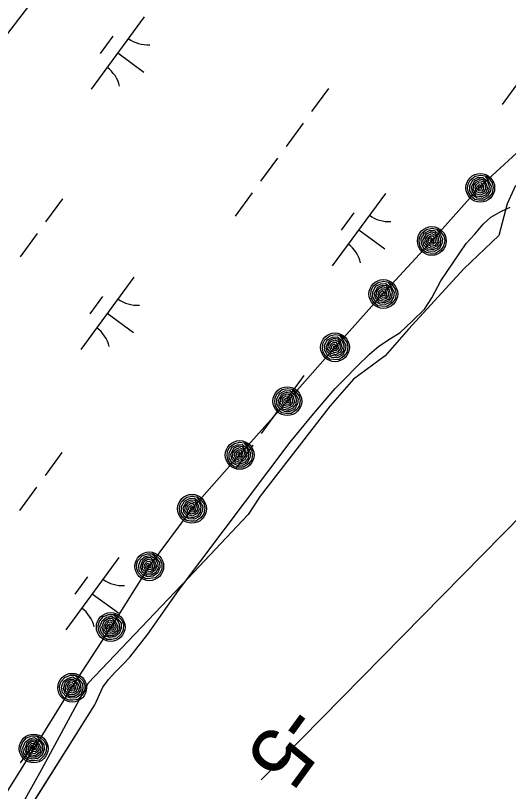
# Model space of a CAD drawing. Extents: x 3905714 to 3926767, y 183354 to 205755.
# Drawn here: x 3911955.9 to 3912230.3, y 187949.4 to 188380.9 of the extents above; entities that cross this region are included whole.
import ezdxf

# ---------------------------------------------------------------- set-up
doc = ezdxf.new("R2010")
doc.units = 0
for name, color, linetype in [('V-RIVR-EDGE', 7, 'Continuous'), ('V-RIVR-RANG', 7, 'Continuous'), ('V-RRAP-FSHR', 7, 'Continuous'), ('V-TOPO-MINR', 7, 'Continuous'), ('V-TOPO-SHOR', 7, 'Continuous'), ('V-UTIL-LINE', 7, 'Continuous'), ('V-WETL-SWMP', 7, 'Continuous')]:
    doc.layers.add(name, color=color, linetype=linetype)

msp = doc.modelspace()

# ---------------------------------------------------------------- linework, layer by layer
at = {"layer": 'V-RIVR-EDGE'}
msp.add_lwpolyline([(3912234.16, 188286.45), (3912229.51, 188276.23), (3912224.87, 188258.58), (3912205.35, 188239.99), (3912174.69, 188206.54), (3912161.68, 188191.67), (3912144.03, 188178.66), (3912131.02, 188163.8), (3912091.99, 188113.62), (3912085.49, 188103.4), (3912052.03, 188068.09), (3911996.28, 188009.55), (3911970.26, 187961.23), (3911928.45, 187886.89), (3911896.86, 187820.92), (3911865.16, 187767.87)], dxfattribs=at)
at = {"layer": 'V-RRAP-FSHR'}
for points in [[(3912243.67, 188312.51), (3912214.58, 188285.92), (3912187.6, 188255.56), (3912160.61, 188226.38), (3912133.74, 188196.41), (3912107.2, 188166.48), (3912080.67, 188136.55), (3912054.13, 188106.62), (3912030.37, 188074.6), (3912008.92, 188040.84), (3911987.47, 188007.77), (3911966.17, 187973.31), (3911944.75, 187939.44), (3911923.63, 187905.47), (3911902.52, 187871.49), (3911881.6, 187837.4), (3911862.53, 187802.25)], [(3912217.66, 188291.74), (3912219.27, 188290.42), (3912221.25, 188287.82), (3912221.8, 188285.3), (3912221.11, 188282.16), (3912219.41, 188279.99), (3912216.63, 188278.17), (3912213.73, 188278.29), (3912211.48, 188278.6), (3912209.28, 188280.41), (3912207.96, 188282.56), (3912207.55, 188284.88), (3912207.78, 188287.09), (3912208.96, 188289.42), (3912211.72, 188291.53), (3912214.84, 188292.17), (3912217.2, 188291.72), (3912219.18, 188288.8), (3912220.6, 188286.2), (3912220.25, 188283.43), (3912218.61, 188280.64), (3912215.84, 188279.25), (3912212.83, 188279.43), (3912210.39, 188280.79), (3912208.8, 188283.43), (3912208.75, 188286.41), (3912210.48, 188289.39), (3912213.25, 188290.81), (3912216.04, 188290.92), (3912218.58, 188288.71), (3912219.49, 188286.1), (3912219.2, 188283.27), (3912217.54, 188281.07), (3912215.08, 188280.11), (3912212.34, 188280.5), (3912210.21, 188282.81), (3912209.67, 188285.6), (3912211.55, 188289), (3912214.17, 188290.09), (3912216.05, 188289.76), (3912217.92, 188287.34), (3912218.56, 188284.53), (3912217.5, 188282.33), (3912214.79, 188280.96), (3912212.52, 188281.65), (3912210.63, 188284.09), (3912211.02, 188286.47), (3912212.55, 188288.36), (3912214.54, 188289.2), (3912216.42, 188288.35), (3912217.21, 188286.52), (3912217.5, 188284.23), (3912216.18, 188282.62), (3912214.3, 188282.08), (3912212.35, 188283.07), (3912211.69, 188284.86), (3912212.11, 188286.58), (3912213.83, 188287.98), (3912215.16, 188287.92), (3912216.23, 188286.23), (3912216.38, 188284.31), (3912215.43, 188283.23), (3912213.87, 188283.35), (3912212.55, 188284.67), (3912213, 188286.25), (3912214.12, 188286.96), (3912215.41, 188285.94), (3912215.34, 188284.3), (3912214.17, 188284.23), (3912213.68, 188285.26), (3912214.08, 188286.01), (3912214.62, 188285.12)], [(3912190.67, 188262.21), (3912192.29, 188260.9), (3912194.27, 188258.29), (3912194.82, 188255.77), (3912194.13, 188252.63), (3912192.42, 188250.46), (3912189.65, 188248.64), (3912186.74, 188248.76), (3912184.49, 188249.07), (3912182.3, 188250.88), (3912180.98, 188253.04), (3912180.57, 188255.36), (3912180.8, 188257.56), (3912181.98, 188259.89), (3912184.74, 188262.01), (3912187.86, 188262.64), (3912190.22, 188262.19), (3912192.19, 188259.28), (3912193.62, 188256.67), (3912193.26, 188253.9), (3912191.63, 188251.11), (3912188.85, 188249.72), (3912185.84, 188249.9), (3912183.4, 188251.26), (3912181.81, 188253.9), (3912181.76, 188256.88), (3912183.49, 188259.86), (3912186.26, 188261.29), (3912189.05, 188261.39), (3912191.6, 188259.19), (3912192.5, 188256.58), (3912192.21, 188253.75), (3912190.55, 188251.54), (3912188.09, 188250.58), (3912185.36, 188250.98), (3912183.23, 188253.28), (3912182.69, 188256.07), (3912184.56, 188259.47), (3912187.19, 188260.56), (3912189.06, 188260.23), (3912190.93, 188257.81), (3912191.58, 188255), (3912190.52, 188252.8), (3912187.8, 188251.44), (3912185.54, 188252.12), (3912183.65, 188254.56), (3912184.04, 188256.94), (3912185.57, 188258.83), (3912187.56, 188259.67), (3912189.44, 188258.82), (3912190.23, 188256.99), (3912190.52, 188254.71), (3912189.2, 188253.09), (3912187.32, 188252.55), (3912185.37, 188253.54), (3912184.71, 188255.34), (3912185.13, 188257.05), (3912186.85, 188258.46), (3912188.17, 188258.39), (3912189.25, 188256.7), (3912189.39, 188254.78), (3912188.45, 188253.7), (3912186.89, 188253.82), (3912185.57, 188255.15), (3912186.01, 188256.72), (3912187.14, 188257.43), (3912188.43, 188256.42), (3912188.36, 188254.77), (3912187.18, 188254.7), (3912186.7, 188255.74), (3912187.1, 188256.48), (3912187.64, 188255.59)], [(3912163.69, 188232.68), (3912165.3, 188231.37), (3912167.28, 188228.77), (3912167.83, 188226.24), (3912167.14, 188223.11), (3912165.44, 188220.94), (3912162.66, 188219.11), (3912159.76, 188219.23), (3912157.51, 188219.55), (3912155.31, 188221.35), (3912154, 188223.51), (3912153.58, 188225.83), (3912153.81, 188228.04), (3912154.99, 188230.37), (3912157.76, 188232.48), (3912160.88, 188233.12), (3912163.23, 188232.66), (3912165.21, 188229.75), (3912166.63, 188227.14), (3912166.28, 188224.37), (3912164.65, 188221.58), (3912161.87, 188220.2), (3912158.86, 188220.37), (3912156.42, 188221.73), (3912154.83, 188224.37), (3912154.78, 188227.35), (3912156.51, 188230.33), (3912159.28, 188231.76), (3912162.07, 188231.86), (3912164.61, 188229.66), (3912165.52, 188227.05), (3912165.23, 188224.22), (3912163.57, 188222.01), (3912161.11, 188221.05), (3912158.38, 188221.45), (3912156.24, 188223.75), (3912155.7, 188226.55), (3912157.58, 188229.94), (3912160.2, 188231.04), (3912162.08, 188230.71), (3912163.95, 188228.28), (3912164.59, 188225.48), (3912163.53, 188223.27), (3912160.82, 188221.91), (3912158.55, 188222.6), (3912156.66, 188225.04), (3912157.05, 188227.41), (3912158.58, 188229.31), (3912160.57, 188230.14), (3912162.46, 188229.29), (3912163.24, 188227.46), (3912163.53, 188225.18), (3912162.22, 188223.57), (3912160.33, 188223.03), (3912158.39, 188224.02), (3912157.72, 188225.81), (3912158.14, 188227.53), (3912159.86, 188228.93), (3912161.19, 188228.86), (3912162.26, 188227.17), (3912162.41, 188225.25), (3912161.46, 188224.18), (3912159.91, 188224.29), (3912158.58, 188225.62), (3912159.03, 188227.19), (3912160.16, 188227.91), (3912161.45, 188226.89), (3912161.37, 188225.25), (3912160.2, 188225.18), (3912159.71, 188226.21), (3912160.12, 188226.95), (3912160.65, 188226.07)], [(3912136.71, 188203.1), (3912138.35, 188201.81), (3912140.37, 188199.24), (3912140.95, 188196.73), (3912140.31, 188193.58), (3912138.64, 188191.39), (3912135.89, 188189.52), (3912132.99, 188189.59), (3912130.73, 188189.87), (3912128.51, 188191.65), (3912127.16, 188193.78), (3912126.71, 188196.1), (3912126.91, 188198.31), (3912128.05, 188200.65), (3912130.78, 188202.81), (3912133.89, 188203.49), (3912136.26, 188203.08), (3912138.28, 188200.19), (3912139.74, 188197.61), (3912139.43, 188194.83), (3912137.84, 188192.02), (3912135.08, 188190.59), (3912132.07, 188190.72), (3912129.61, 188192.04), (3912127.98, 188194.66), (3912127.88, 188197.64), (3912129.57, 188200.64), (3912132.32, 188202.11), (3912135.11, 188202.26), (3912137.68, 188200.09), (3912138.63, 188197.5), (3912138.38, 188194.66), (3912136.75, 188192.43), (3912134.31, 188191.43), (3912131.57, 188191.79), (3912129.4, 188194.06), (3912128.82, 188196.85), (3912130.65, 188200.27), (3912133.25, 188201.4), (3912135.14, 188201.1), (3912137.04, 188198.71), (3912137.73, 188195.91), (3912136.7, 188193.69), (3912134.01, 188192.29), (3912131.73, 188192.94), (3912129.8, 188195.35), (3912130.16, 188197.73), (3912131.66, 188199.65), (3912133.64, 188200.51), (3912135.53, 188199.7), (3912136.35, 188197.88), (3912136.67, 188195.6), (3912135.38, 188193.97), (3912133.5, 188193.4), (3912131.54, 188194.36), (3912130.85, 188196.14), (3912131.25, 188197.86), (3912132.94, 188199.29), (3912134.27, 188199.25), (3912135.37, 188197.57), (3912135.55, 188195.65), (3912134.62, 188194.56), (3912133.06, 188194.65), (3912131.71, 188195.96), (3912132.14, 188197.54), (3912133.25, 188198.27), (3912134.56, 188197.27), (3912134.51, 188195.63), (3912133.33, 188195.54), (3912132.84, 188196.57), (3912133.23, 188197.32), (3912133.78, 188196.44)], [(3912110.18, 188173.17), (3912111.81, 188171.88), (3912113.83, 188169.31), (3912114.42, 188166.8), (3912113.78, 188163.65), (3912112.11, 188161.45), (3912109.36, 188159.59), (3912106.45, 188159.66), (3912104.2, 188159.94), (3912101.98, 188161.72), (3912100.62, 188163.85), (3912100.18, 188166.17), (3912100.37, 188168.38), (3912101.52, 188170.72), (3912104.25, 188172.88), (3912107.36, 188173.56), (3912109.72, 188173.14), (3912111.74, 188170.26), (3912113.2, 188167.68), (3912112.89, 188164.9), (3912111.3, 188162.09), (3912108.55, 188160.66), (3912105.53, 188160.79), (3912103.07, 188162.11), (3912101.44, 188164.73), (3912101.35, 188167.71), (3912103.03, 188170.71), (3912105.78, 188172.18), (3912108.57, 188172.33), (3912111.15, 188170.16), (3912112.09, 188167.57), (3912111.85, 188164.73), (3912110.22, 188162.5), (3912107.77, 188161.5), (3912105.04, 188161.86), (3912102.87, 188164.13), (3912102.29, 188166.92), (3912104.11, 188170.34), (3912106.72, 188171.47), (3912108.6, 188171.17), (3912110.5, 188168.78), (3912111.19, 188165.98), (3912110.16, 188163.76), (3912107.47, 188162.36), (3912105.19, 188163.01), (3912103.27, 188165.42), (3912103.62, 188167.8), (3912105.12, 188169.72), (3912107.1, 188170.58), (3912109, 188169.76), (3912109.81, 188167.95), (3912110.13, 188165.67), (3912108.84, 188164.04), (3912106.97, 188163.47), (3912105, 188164.43), (3912104.32, 188166.21), (3912104.71, 188167.93), (3912106.41, 188169.36), (3912107.74, 188169.32), (3912108.83, 188167.64), (3912109.01, 188165.72), (3912108.08, 188164.63), (3912106.52, 188164.73), (3912105.18, 188166.03), (3912105.6, 188167.61), (3912106.72, 188168.34), (3912108.02, 188167.34), (3912107.98, 188165.7), (3912106.8, 188165.61), (3912106.3, 188166.64), (3912106.69, 188167.39), (3912107.24, 188166.51)], [(3912083.64, 188143.24), (3912085.27, 188141.95), (3912087.29, 188139.38), (3912087.88, 188136.86), (3912087.24, 188133.72), (3912085.57, 188131.52), (3912082.82, 188129.66), (3912079.92, 188129.73), (3912077.66, 188130.01), (3912075.44, 188131.79), (3912074.09, 188133.92), (3912073.64, 188136.24), (3912073.84, 188138.45), (3912074.98, 188140.79), (3912077.71, 188142.95), (3912080.82, 188143.63), (3912083.19, 188143.21), (3912085.21, 188140.33), (3912086.67, 188137.74), (3912086.36, 188134.97), (3912084.77, 188132.16), (3912082.01, 188130.73), (3912079, 188130.86), (3912076.54, 188132.18), (3912074.91, 188134.8), (3912074.81, 188137.78), (3912076.5, 188140.78), (3912079.25, 188142.25), (3912082.04, 188142.4), (3912084.61, 188140.23), (3912085.56, 188137.64), (3912085.31, 188134.8), (3912083.68, 188132.57), (3912081.23, 188131.57), (3912078.5, 188131.93), (3912076.33, 188134.2), (3912075.75, 188136.99), (3912077.58, 188140.41), (3912080.18, 188141.54), (3912082.06, 188141.24), (3912083.97, 188138.85), (3912084.66, 188136.05), (3912083.63, 188133.83), (3912080.94, 188132.43), (3912078.66, 188133.08), (3912076.73, 188135.49), (3912077.08, 188137.87), (3912078.59, 188139.79), (3912080.56, 188140.65), (3912082.46, 188139.83), (3912083.27, 188138.02), (3912083.6, 188135.74), (3912082.31, 188134.11), (3912080.43, 188133.54), (3912078.47, 188134.49), (3912077.78, 188136.28), (3912078.18, 188138), (3912079.87, 188139.43), (3912081.2, 188139.39), (3912082.3, 188137.71), (3912082.47, 188135.79), (3912081.54, 188134.7), (3912079.98, 188134.79), (3912078.64, 188136.1), (3912079.06, 188137.68), (3912080.18, 188138.41), (3912081.48, 188137.41), (3912081.44, 188135.77), (3912080.26, 188135.68), (3912079.77, 188136.71), (3912080.16, 188137.46), (3912080.71, 188136.58)], [(3912057.11, 188113.31), (3912058.74, 188112.02), (3912060.76, 188109.45), (3912061.35, 188106.93), (3912060.71, 188103.79), (3912059.03, 188101.59), (3912056.29, 188099.73), (3912053.38, 188099.8), (3912051.12, 188100.08), (3912048.9, 188101.86), (3912047.55, 188103.99), (3912047.1, 188106.3), (3912047.3, 188108.52), (3912048.45, 188110.86), (3912051.18, 188113.02), (3912054.29, 188113.7), (3912056.65, 188113.28), (3912058.67, 188110.4), (3912060.13, 188107.81), (3912059.82, 188105.04), (3912058.23, 188102.23), (3912055.48, 188100.8), (3912052.46, 188100.93), (3912050, 188102.25), (3912048.37, 188104.87), (3912048.27, 188107.85), (3912049.96, 188110.85), (3912052.71, 188112.32), (3912055.5, 188112.47), (3912058.08, 188110.3), (3912059.02, 188107.71), (3912058.77, 188104.87), (3912057.15, 188102.64), (3912054.7, 188101.64), (3912051.96, 188102), (3912049.79, 188104.27), (3912049.21, 188107.05), (3912051.04, 188110.48), (3912053.64, 188111.61), (3912055.53, 188111.31), (3912057.43, 188108.92), (3912058.12, 188106.12), (3912057.09, 188103.9), (3912054.4, 188102.5), (3912052.12, 188103.15), (3912050.19, 188105.56), (3912050.55, 188107.94), (3912052.05, 188109.86), (3912054.03, 188110.72), (3912055.92, 188109.9), (3912056.74, 188108.09), (3912057.06, 188105.81), (3912055.77, 188104.17), (3912053.9, 188103.61), (3912051.93, 188104.57), (3912051.25, 188106.35), (3912051.64, 188108.07), (3912053.34, 188109.5), (3912054.67, 188109.46), (3912055.76, 188107.78), (3912055.94, 188105.86), (3912055.01, 188104.77), (3912053.45, 188104.86), (3912052.11, 188106.17), (3912052.53, 188107.75), (3912053.65, 188108.48), (3912054.95, 188107.48), (3912054.9, 188105.84), (3912053.73, 188105.75), (3912053.23, 188106.78), (3912053.62, 188107.53), (3912054.17, 188106.65)], [(3912032.24, 188081.68), (3912034.06, 188080.67), (3912036.46, 188078.45), (3912037.44, 188076.06), (3912037.31, 188072.85), (3912036, 188070.42), (3912033.59, 188068.14), (3912030.71, 188067.75), (3912028.44, 188067.67), (3912025.96, 188069.07), (3912024.29, 188070.96), (3912023.48, 188073.18), (3912023.32, 188075.39), (3912024.08, 188077.89), (3912026.43, 188080.45), (3912029.39, 188081.62), (3912031.8, 188081.58), (3912034.25, 188079.05), (3912036.1, 188076.73), (3912036.23, 188073.95), (3912035.11, 188070.92), (3912032.62, 188069.07), (3912029.62, 188068.72), (3912026.98, 188069.63), (3912024.96, 188071.96), (3912024.39, 188074.89), (3912025.58, 188078.12), (3912028.06, 188080.01), (3912030.79, 188080.59), (3912033.68, 188078.86), (3912035.02, 188076.45), (3912035.23, 188073.61), (3912033.98, 188071.15), (3912031.72, 188069.78), (3912028.96, 188069.69), (3912026.46, 188071.59), (3912025.44, 188074.25), (3912026.7, 188077.92), (3912029.09, 188079.45), (3912031, 188079.45), (3912033.26, 188077.39), (3912034.38, 188074.74), (3912033.72, 188072.39), (3912031.29, 188070.57), (3912028.93, 188070.85), (3912026.65, 188072.93), (3912026.62, 188075.34), (3912027.8, 188077.47), (3912029.61, 188078.64), (3912031.61, 188078.13), (3912032.71, 188076.46), (3912033.39, 188074.26), (3912032.37, 188072.45), (3912030.61, 188071.59), (3912028.52, 188072.22), (3912027.56, 188073.88), (3912027.68, 188075.64), (3912029.12, 188077.32), (3912030.44, 188077.49), (3912031.79, 188076.01), (3912032.27, 188074.14), (3912031.53, 188072.92), (3912029.97, 188072.76), (3912028.44, 188073.84), (3912028.6, 188075.46), (3912029.59, 188076.36), (3912031.04, 188075.58), (3912031.25, 188073.96), (3912030.1, 188073.68), (3912029.45, 188074.61), (3912029.72, 188075.42), (3912030.4, 188074.64)], [(3912010.79, 188047.92), (3912012.61, 188046.9), (3912015.01, 188044.68), (3912015.99, 188042.3), (3912015.86, 188039.08), (3912014.56, 188036.65), (3912012.14, 188034.38), (3912009.26, 188033.99), (3912006.99, 188033.91), (3912004.51, 188035.3), (3912002.84, 188037.2), (3912002.03, 188039.41), (3912001.87, 188041.63), (3912002.63, 188044.13), (3912004.98, 188046.69), (3912007.95, 188047.86), (3912010.35, 188047.82), (3912012.8, 188045.29), (3912014.65, 188042.97), (3912014.79, 188040.18), (3912013.66, 188037.15), (3912011.17, 188035.3), (3912008.17, 188034.96), (3912005.53, 188035.87), (3912003.51, 188038.2), (3912002.94, 188041.12), (3912004.13, 188044.35), (3912006.61, 188046.24), (3912009.34, 188046.83), (3912012.23, 188045.1), (3912013.57, 188042.69), (3912013.78, 188039.85), (3912012.53, 188037.39), (3912010.27, 188036.02), (3912007.51, 188035.93), (3912005.01, 188037.83), (3912003.99, 188040.49), (3912005.25, 188044.16), (3912007.64, 188045.69), (3912009.55, 188045.69), (3912011.81, 188043.63), (3912012.93, 188040.98), (3912012.27, 188038.62), (3912009.84, 188036.81), (3912007.48, 188037.09), (3912005.2, 188039.17), (3912005.17, 188041.58), (3912006.35, 188043.71), (3912008.17, 188044.87), (3912010.16, 188044.36), (3912011.26, 188042.7), (3912011.94, 188040.5), (3912010.92, 188038.68), (3912009.16, 188037.83), (3912007.07, 188038.46), (3912006.11, 188040.11), (3912006.23, 188041.88), (3912007.67, 188043.56), (3912008.99, 188043.72), (3912010.34, 188042.24), (3912010.82, 188040.38), (3912010.08, 188039.15), (3912008.52, 188039), (3912006.99, 188040.08), (3912007.16, 188041.7), (3912008.14, 188042.6), (3912009.59, 188041.82), (3912009.8, 188040.19), (3912008.66, 188039.92), (3912008, 188040.85), (3912008.27, 188041.65), (3912008.95, 188040.87)], [(3911989.34, 188014.15), (3911991.16, 188013.14), (3911993.56, 188010.92), (3911994.54, 188008.53), (3911994.41, 188005.32), (3911993.11, 188002.89), (3911990.69, 188000.61), (3911987.81, 188000.23), (3911985.54, 188000.14), (3911983.06, 188001.54), (3911981.39, 188003.44), (3911980.58, 188005.65), (3911980.42, 188007.86), (3911981.18, 188010.36), (3911983.53, 188012.92), (3911986.5, 188014.09), (3911988.9, 188014.06), (3911991.35, 188011.53), (3911993.2, 188009.21), (3911993.34, 188006.42), (3911992.21, 188003.39), (3911989.72, 188001.54), (3911986.72, 188001.19), (3911984.08, 188002.11), (3911982.06, 188004.43), (3911981.49, 188007.36), (3911982.68, 188010.59), (3911985.16, 188012.48), (3911987.89, 188013.07), (3911990.78, 188011.34), (3911992.12, 188008.93), (3911992.33, 188006.09), (3911991.08, 188003.63), (3911988.82, 188002.25), (3911986.06, 188002.17), (3911983.56, 188004.07), (3911982.54, 188006.73), (3911983.8, 188010.4), (3911986.19, 188011.93), (3911988.1, 188011.93), (3911990.36, 188009.87), (3911991.48, 188007.21), (3911990.82, 188004.86), (3911988.39, 188003.05), (3911986.04, 188003.33), (3911983.75, 188005.4), (3911983.72, 188007.81), (3911984.9, 188009.94), (3911986.71, 188011.11), (3911988.71, 188010.6), (3911989.81, 188008.94), (3911990.49, 188006.74), (3911989.47, 188004.92), (3911987.71, 188004.06), (3911985.62, 188004.7), (3911984.66, 188006.35), (3911984.78, 188008.11), (3911986.23, 188009.79), (3911987.54, 188009.96), (3911988.89, 188008.48), (3911989.37, 188006.62), (3911988.63, 188005.39), (3911987.07, 188005.23), (3911985.54, 188006.31), (3911985.71, 188007.94), (3911986.69, 188008.84), (3911988.14, 188008.06), (3911988.35, 188006.43), (3911987.21, 188006.15), (3911986.55, 188007.09), (3911986.82, 188007.89), (3911987.5, 188007.11)], [(3911967.89, 187980.39), (3911969.71, 187979.38), (3911972.11, 187977.16), (3911973.09, 187974.77), (3911972.96, 187971.56), (3911971.66, 187969.13), (3911969.24, 187966.85), (3911966.36, 187966.46), (3911964.09, 187966.38), (3911961.61, 187967.78), (3911959.94, 187969.67), (3911959.13, 187971.89), (3911958.97, 187974.1), (3911959.73, 187976.6), (3911962.08, 187979.16), (3911965.05, 187980.33), (3911967.45, 187980.29), (3911969.9, 187977.77), (3911971.75, 187975.45), (3911971.89, 187972.66), (3911970.76, 187969.63), (3911968.27, 187967.78), (3911965.27, 187967.43), (3911962.63, 187968.35), (3911960.61, 187970.67), (3911960.04, 187973.6), (3911961.23, 187976.83), (3911963.71, 187978.72), (3911966.44, 187979.31), (3911969.33, 187977.58), (3911970.67, 187975.16), (3911970.88, 187972.33), (3911969.63, 187969.86), (3911967.37, 187968.49), (3911964.61, 187968.4), (3911962.11, 187970.31), (3911961.09, 187972.96), (3911962.35, 187976.63), (3911964.75, 187978.16), (3911966.65, 187978.17), (3911968.91, 187976.11), (3911970.04, 187973.45), (3911969.37, 187971.1), (3911966.94, 187969.29), (3911964.58, 187969.57), (3911962.3, 187971.64), (3911962.27, 187974.05), (3911963.45, 187976.18), (3911965.27, 187977.35), (3911967.27, 187976.84), (3911968.36, 187975.18), (3911969.04, 187972.98), (3911968.02, 187971.16), (3911966.27, 187970.3), (3911964.17, 187970.94), (3911963.21, 187972.59), (3911963.33, 187974.35), (3911964.77, 187976.03), (3911966.1, 187976.2), (3911967.44, 187974.72), (3911967.92, 187972.85), (3911967.18, 187971.63), (3911965.62, 187971.47), (3911964.09, 187972.55), (3911964.26, 187974.18), (3911965.24, 187975.08), (3911966.69, 187974.3), (3911966.9, 187972.67), (3911965.76, 187972.39), (3911965.1, 187973.33), (3911965.37, 187974.13), (3911966.05, 187973.35)]]:
    msp.add_lwpolyline(points, dxfattribs=at)
for centre in [(3912214.58, 188285.09), (3912187.6, 188255.57), (3912160.61, 188226.04), (3912133.74, 188196.41), (3912107.2, 188166.48), (3912080.67, 188136.55), (3912054.13, 188106.62), (3912030.37, 188074.6), (3912008.92, 188040.84), (3911987.47, 188007.08), (3911966.02, 187973.31)]:
    msp.add_circle(centre, 8, dxfattribs=at)
at = {"layer": 'V-TOPO-MINR'}
msp.add_lwpolyline([(3912092.66, 187955.85), (3912664.69, 188537.15)], dxfattribs=at)
at = {"layer": 'V-TOPO-SHOR'}
msp.add_lwpolyline([(3911959.31, 187932.86), (3912000.15, 187997.59), (3912004.58, 188007.31), (3912007.76, 188011.62), (3912011.36, 188015.79), (3912015.38, 188019.82), (3912019.54, 188024.13), (3912029.51, 188036.91), (3912046.68, 188061.23), (3912108.86, 188143.62), (3912121.74, 188159.46), (3912133.79, 188173.5), (3912139.06, 188178.78), (3912145.99, 188186.01), (3912152.92, 188192.54), (3912158.18, 188196.99), (3912164.56, 188201.3), (3912169.97, 188204.64), (3912176.62, 188210.9), (3912183.55, 188217.71), (3912187.7, 188223.96), (3912192.54, 188233.4), (3912206.67, 188254.1), (3912211.52, 188259.38), (3912216.22, 188264.94), (3912220.52, 188268.7), (3912226.35, 188272.04), (3912231.2, 188274.4)], dxfattribs=at)
at = {"layer": 'V-UTIL-LINE'}
msp.add_lwpolyline([(3920382.72, 200123.13), (3919431.34, 198911.04), (3917639.74, 196643.01), (3912670.96, 189304.15), (3911629.35, 187953.28)], dxfattribs=at)
at = {"layer": 'V-WETL-SWMP'}
for p, q in [((3912027.56, 188380.29), (3911998.01, 188339.96)), ((3912010.11, 188369.53), (3912003.01, 188359.85)), ((3912012.78, 188360.13), (3912027.3, 188349.49)), ((3912236.27, 188344.43), (3912226.81, 188331.53)), ((3912130.11, 188340.4), (3912120.65, 188327.49)), ((3912115.92, 188321.04), (3912106.47, 188308.13)), ((3912101.74, 188301.68), (3912092.28, 188288.77)), ((3912087.56, 188282.32), (3912078.1, 188269.41)), ((3912161.74, 188281.99), (3912132.19, 188241.65)), ((3911982.14, 188279.02), (3911972.69, 188266.12)), ((3912226.34, 188272.04), (3912231.2, 188274.4)), ((3912144.29, 188271.22), (3912137.19, 188261.54)), ((3912216.22, 188264.94), (3912220.52, 188268.7)), ((3912220.52, 188268.7), (3912226.34, 188272.04)), ((3912211.51, 188259.39), (3912216.22, 188264.94)), ((3911967.96, 188259.66), (3911958.5, 188246.76)), ((3912146.96, 188261.82), (3912161.48, 188251.18)), ((3912206.67, 188254.1), (3912211.51, 188259.39)), ((3912192.54, 188233.4), (3912206.67, 188254.1)), ((3912021.78, 188235.47), (3911992.23, 188195.14)), ((3912187.7, 188223.96), (3912192.54, 188233.4)), ((3912004.33, 188224.71), (3911997.24, 188215.03)), ((3912183.55, 188217.71), (3912187.7, 188223.96)), ((3912176.62, 188210.9), (3912183.55, 188217.71)), ((3912007.01, 188215.31), (3912021.53, 188204.67)), ((3912169.97, 188204.64), (3912176.62, 188210.9)), ((3912164.56, 188201.3), (3912169.97, 188204.64)), ((3912158.18, 188196.99), (3912164.56, 188201.3)), ((3912152.92, 188192.54), (3912158.18, 188196.99)), ((3912145.99, 188186.01), (3912152.92, 188192.54)), ((3912139.06, 188178.78), (3912145.99, 188186.01)), ((3912116.32, 188180.72), (3912106.87, 188167.81)), ((3912133.79, 188173.5), (3912139.06, 188178.78)), ((3912121.74, 188159.46), (3912133.79, 188173.5)), ((3912102.14, 188161.36), (3912092.68, 188148.45)), ((3912108.86, 188143.62), (3912121.74, 188159.46)), ((3912046.68, 188061.23), (3912108.86, 188143.62)), ((3912087.95, 188142), (3912078.5, 188129.09)), ((3911981.79, 188137.96), (3911972.34, 188125.05)), ((3911967.61, 188118.6), (3911958.15, 188105.69)), ((3912013.42, 188079.55), (3911983.87, 188039.22)), ((3911995.97, 188068.78), (3911988.88, 188059.1)), ((3912029.51, 188036.91), (3912046.68, 188061.23)), ((3911998.65, 188059.38), (3912013.17, 188048.75)), ((3912019.54, 188024.13), (3912029.51, 188036.91)), ((3912015.38, 188019.82), (3912019.54, 188024.13)), ((3912011.36, 188015.79), (3912015.38, 188019.82)), ((3912007.76, 188011.62), (3912011.36, 188015.79)), ((3912004.58, 188007.31), (3912007.76, 188011.62)), ((3912000.15, 187997.59), (3912004.58, 188007.31)), ((3911959.31, 187932.86), (3912000.15, 187997.59)), ((3911968.01, 187978.28), (3911958.55, 187965.37))]:
    msp.add_line(p, q, dxfattribs=at)
for centre, start, end in [((3912029.3, 188382.27), 233, 274.5436), ((3911996.65, 188337.7), 13, 54.5436), ((3912163.48, 188283.96), 233, 274.5436), ((3912130.83, 188239.4), 13, 54.5436), ((3912023.52, 188237.45), 233, 274.5436), ((3911990.88, 188192.88), 13, 54.5436), ((3912015.17, 188081.52), 233, 274.5436), ((3911982.52, 188036.96), 13, 54.5436)]:
    msp.add_arc(centre, 17.62, start, end, dxfattribs=at)

# ---------------------------------------------------------------- texts
at = {"layer": 'V-RIVR-RANG'}
msp.add_text('-5', height=33.5, rotation=233.8683, dxfattribs=at).set_placement((3912106.43, 188000.27))

doc.saveas('drawing.dxf')
